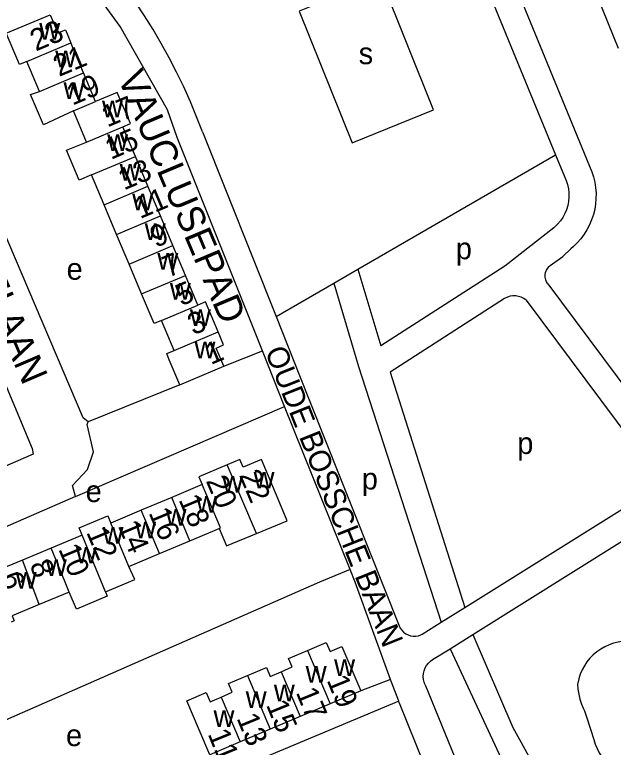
# Model space of a CAD drawing. Extents: x 157768 to 159790, y 387230 to 389604.
# Drawn here: x 158864.1 to 158974.5, y 388469.5 to 388604.7 of the extents above; entities that cross this region are included whole.
import ezdxf

# ---------------------------------------------------------------- set-up
doc = ezdxf.new("R2010")
doc.units = 0
for name, color, linetype in [('BLT_Basislijn', 7, 'Continuous'), ('BLT_Bebouwing', 7, 'Continuous'), ('BLT_Centroide', 7, 'Continuous'), ('BLT_Huisnummer', 7, 'Continuous'), ('BLT_Huisnummer_ tussenligend', 7, 'Continuous'), ('BLT_Onderverdeling_panden', 7, 'Continuous'), ('BLT_Straatnaam', 7, 'Continuous'), ('BLT_Straatnaam_verkleind', 7, 'Continuous')]:
    doc.layers.add(name, color=color, linetype=linetype)

msp = doc.modelspace()

# ---------------------------------------------------------------- linework, layer by layer
at = {"layer": 'BLT_Basislijn'}
for p, q in [((158975.41, 388598.44), (158950.82, 388659.43)), ((158945.06, 388637.67), (158970.49, 388575.7)), ((158940.42, 388635.8), (158963.8, 388578.82)), ((158898.7, 388583.02), (158912.26, 388549)), ((158927.34, 388557.72), (158963.8, 388578.82)), ((158963.8, 388578.82), (158965.76, 388574.06)), ((158963.46, 388565.36), (158954.48, 388558.29)), ((158954.48, 388558.29), (158931.57, 388543.58)), ((158922.89, 388555.15), (158927.34, 388557.72)), ((158927.34, 388557.72), (158931.57, 388543.58)), ((158912.26, 388549), (158922.89, 388555.15)), ((158922.89, 388555.15), (158927.49, 388539.78)), ((158962.37, 388554.99), (158987.75, 388521)), ((158954.4, 388552.33), (158933.31, 388538.75)), ((158958.37, 388552), (158983.58, 388518.22)), ((158912.26, 388549), (158916.6, 388538.1)), ((158902.62, 388539.82), (158909.76, 388542.67)), ((158913.81, 388532.41), (158909.76, 388542.67)), ((158927.49, 388539.78), (158942.71, 388492.62)), ((158916.6, 388538.1), (158918.5, 388533.34)), ((158933.31, 388538.75), (158947.09, 388495.36)), ((158894.53, 388536.41), (158877.6, 388529.55)), ((158918.5, 388533.34), (158934.98, 388491.97)), ((158875.29, 388515.8), (158913.81, 388532.41)), ((158925.92, 388502.32), (158913.81, 388532.41)), ((158875.29, 388515.8), (158843.47, 388502.02)), ((158942.71, 388492.62), (158947.09, 388495.36)), ((158939.2, 388490.42), (158942.71, 388492.62)), ((158944.35, 388487.74), (158948.53, 388490.36)), ((158941.12, 388485.73), (158944.35, 388487.74)), ((158933.36, 388482.07), (158927.87, 388479.94)), ((158939.77, 388481.05), (158952.53, 388449.95)), ((158934.99, 388477.78), (158934.88, 388478.07)), ((158934.99, 388477.78), (158941.62, 388461.3)), ((158969.15, 388476.3), (158969.56, 388475.02)), ((158969.56, 388475.02), (158970.86, 388470.97))]:
    msp.add_line(p, q, dxfattribs=at)
for points in [[(158898.7, 388583.02), (158897.62, 388585.82), (158896.46, 388588.59), (158895.23, 388591.32), (158893.93, 388594.02), (158892.55, 388596.69), (158891.11, 388599.32), (158889.59, 388601.9), (158888.01, 388604.45), (158886.36, 388606.96), (158884.64, 388609.41), (158882.86, 388611.83), (158881.01, 388614.19), (158879.11, 388616.5), (158877.14, 388618.77), (158875.11, 388620.98), (158873.02, 388623.13), (158870.88, 388625.23), (158870.12, 388625.94)], [(158909.76, 388542.67), (158894.06, 388582.03), (158892.27, 388587.1), (158883.51, 388602.46), (158877.81, 388610.42), (158874.98, 388613.54)], [(158916.51, 388605.32), (158926.27, 388581.03), (158941.32, 388587.12), (158931.57, 388611.37), (158916.51, 388605.32)], [(158877.6, 388529.55), (158876.7, 388530.29), (158849.23, 388594.74), (158848.78, 388595.18)], [(158970.49, 388575.7), (158970.8, 388574.74), (158971.03, 388573.76), (158971.19, 388572.76), (158971.27, 388571.76), (158971.26, 388570.75), (158971.18, 388569.75), (158971.02, 388568.75), (158970.78, 388567.78), (158970.46, 388566.82), (158970.07, 388565.89), (158969.6, 388565), (158969.07, 388564.15), (158968.47, 388563.34), (158967.81, 388562.58), (158967.09, 388561.88), (158966.63, 388561.49)], [(158965.76, 388574.06), (158966, 388573.32), (158966.17, 388572.55), (158966.26, 388571.77), (158966.27, 388570.99), (158966.2, 388570.21), (158966.05, 388569.44), (158965.82, 388568.69), (158965.52, 388567.97), (158965.14, 388567.28), (158964.7, 388566.64), (158964.19, 388566.04), (158963.63, 388565.49), (158963.46, 388565.36)], [(158962.83, 388558.39), (158965.14, 388560.05), (158966.63, 388561.49)], [(158962.37, 388554.99), (158962.14, 388555.37), (158961.99, 388555.78), (158961.9, 388556.22), (158961.9, 388556.66), (158961.98, 388557.1), (158962.13, 388557.51), (158962.36, 388557.89), (158962.65, 388558.23), (158962.83, 388558.39)], [(158958.37, 388552), (158957.94, 388552.3), (158957.48, 388552.54), (158956.98, 388552.71), (158956.46, 388552.79), (158955.94, 388552.8), (158955.42, 388552.73), (158954.92, 388552.58), (158954.4, 388552.33)], [(158856.2, 388551.05), (158867.29, 388524.65), (158867.48, 388523.59), (158843.07, 388513.05)], [(158875.29, 388515.8), (158874.72, 388517.84), (158877.52, 388520.77), (158878.59, 388524.05), (158877.42, 388529.06), (158877.6, 388529.55)], [(158948.53, 388490.36), (158985.19, 388513.29), (158991.08, 388517.21), (159005.1, 388524.86)], [(158947.09, 388495.36), (158982.47, 388517.49), (158983.58, 388518.22)], [(158925.92, 388502.32), (158920.27, 388500), (158858.27, 388472.75)], [(158933.36, 388482.07), (158926.83, 388500), (158925.92, 388502.32)], [(158934.98, 388491.97), (158935.18, 388491.53), (158935.46, 388491.13), (158935.79, 388490.78), (158936.18, 388490.49), (158936.61, 388490.27), (158937.07, 388490.12), (158937.55, 388490.05), (158938.04, 388490.05), (158938.51, 388490.14), (158938.97, 388490.31), (158939.2, 388490.42)], [(158948.53, 388490.36), (158955.94, 388473.21), (158957.78, 388469.86)], [(158977.06, 388489.15), (158976.2, 388489.1), (158975.34, 388488.97), (158974.49, 388488.76), (158973.68, 388488.47), (158972.89, 388488.11), (158972.13, 388487.68), (158971.42, 388487.18), (158970.76, 388486.62), (158970.15, 388486), (158969.6, 388485.32), (158969.12, 388484.6), (158968.7, 388483.84), (158968.36, 388483.04), (158968.09, 388482.21), (158967.9, 388481.37), (158967.88, 388481.24)], [(158944.35, 388487.74), (158955.86, 388463.01), (158960.62, 388453.61), (158960.67, 388453.29), (158960.25, 388452.97), (158952.53, 388449.95)], [(158939.77, 388481.05), (158939.58, 388481.55), (158939.45, 388482.08), (158939.41, 388482.61), (158939.45, 388483.15), (158939.56, 388483.68), (158939.76, 388484.19), (158940.02, 388484.66), (158940.35, 388485.08), (158940.74, 388485.46), (158941.12, 388485.73)], [(158934.88, 388478.07), (158933.55, 388481.54), (158933.36, 388482.07)], [(158967.88, 388481.24), (158967.94, 388480.29), (158968.08, 388479.36), (158968.3, 388478.43), (158968.6, 388477.53), (158968.97, 388476.66), (158969.15, 388476.3)], [(158934.88, 388478.07), (158911.01, 388468.07), (158915.99, 388456.66)], [(158970.86, 388470.97), (158971.12, 388470.14), (158971.46, 388469.34), (158971.86, 388468.56), (158972.34, 388467.83), (158972.88, 388467.15), (158973.49, 388466.52), (158974.14, 388465.94), (158974.85, 388465.43), (158975.6, 388464.99), (158976.39, 388464.61), (158977.21, 388464.31), (158978.06, 388464.09), (158978.92, 388463.94), (158979.79, 388463.88), (158980.66, 388463.89), (158981.53, 388463.98), (158982.38, 388464.16), (158983.22, 388464.41), (158983.99, 388464.71)], [(158957.78, 388469.86), (158966.52, 388453.88), (158973.85, 388442.88), (158989.79, 388420.06), (158996.14, 388409.83)]]:
    msp.add_lwpolyline(points, dxfattribs=at)
at = {"layer": 'BLT_Bebouwing'}
for p, q in [((158876.76, 388593.92), (158874.43, 388599.44)), ((158868.65, 388590.5), (158866.33, 388596.02)), ((158878.99, 388588.62), (158876.76, 388593.92)), ((158877.33, 388581.17), (158874.91, 388586.9)), ((158886.32, 388578.5), (158884.01, 388583.98)), ((158888.63, 388573.02), (158886.32, 388578.5)), ((158880.55, 388569.61), (158878.24, 388575.1)), ((158890.94, 388567.54), (158888.63, 388573.02)), ((158882.86, 388564.13), (158880.55, 388569.61)), ((158893.25, 388562.06), (158890.94, 388567.54)), ((158885.17, 388558.65), (158882.86, 388564.13)), ((158895.56, 388556.58), (158893.25, 388562.06)), ((158887.48, 388553.17), (158885.17, 388558.65)), ((158897.87, 388551.1), (158895.56, 388556.58)), ((158893.49, 388542.73), (158891.15, 388548.27)), ((158894.53, 388536.41), (158902.62, 388539.82)), ((158898.64, 388517.99), (158893.02, 388515.63)), ((158893.02, 388515.63), (158887.4, 388513.27)), ((158887.4, 388513.27), (158881.78, 388510.91)), ((158876.49, 388508.7), (158870.78, 388506.3)), ((158890.76, 388505.27), (158896.38, 388507.64)), ((158870.78, 388506.3), (158865.49, 388504.07)), ((158865.49, 388504.07), (158859.91, 388501.73)), ((158874.13, 388498.18), (158868.6, 388495.86)), ((158927.87, 388479.94), (158922.25, 388477.56)), ((158922.25, 388477.56), (158916.72, 388475.22)), ((158916.72, 388475.22), (158911.19, 388472.88)), ((158911.19, 388472.88), (158905.66, 388470.54)), ((158905.66, 388470.54), (158900.04, 388468.16))]:
    msp.add_line(p, q, dxfattribs=at)
for points in [[(158866.33, 388596.02), (158864.95, 388595.44), (158864.45, 388596.63), (158862.51, 388601.23), (158870.62, 388604.65), (158872.04, 388601.29), (158873.41, 388601.87), (158874.43, 388599.44)], [(158874.91, 388586.9), (158869.38, 388584.31), (158867.01, 388589.94), (158868.65, 388590.5)], [(158884.01, 388583.98), (158885.4, 388584.57), (158882.98, 388590.3), (158878.99, 388588.62)], [(158878.24, 388575.1), (158875.96, 388574.13), (158873.64, 388579.64), (158877.33, 388581.17)], [(158891.15, 388548.27), (158889.79, 388547.69), (158887.48, 388553.17)], [(158901.6, 388546.15), (158899.26, 388551.68), (158897.87, 388551.1)], [(158902.62, 388539.82), (158901.2, 388543.18), (158902.6, 388543.77), (158901.6, 388546.15)], [(158894.53, 388536.41), (158892.58, 388541.02), (158892.11, 388542.15), (158893.49, 388542.73)], [(158908.64, 388508.96), (158914.33, 388511.3), (158912.96, 388514.57), (158909.57, 388522.63), (158906.19, 388521.21), (158905.6, 388522.61), (158903.28, 388521.63)], [(158903.28, 388521.63), (158898.03, 388519.42), (158898.64, 388517.99)], [(158876.49, 388508.7), (158875.94, 388510), (158881.22, 388512.22), (158881.78, 388510.91)], [(158896.38, 388507.64), (158901.78, 388509.91)], [(158901.78, 388509.91), (158903.13, 388506.69), (158908.64, 388508.96)], [(158885.14, 388502.91), (158890.76, 388505.27)], [(158880.82, 388498.2), (158886.22, 388500.5), (158885.14, 388502.91)], [(158880.82, 388498.2), (158881.14, 388497.44), (158875.44, 388495.04), (158874.13, 388498.18)], [(158868.6, 388495.86), (158863.62, 388493.77), (158863.99, 388492.89), (158863.39, 388492.64)], [(158918.08, 388487.41), (158921.53, 388488.87), (158922.23, 388487.2), (158924.4, 388488.12), (158927.87, 388479.94)], [(158913.21, 388483.5), (158915.25, 388484.37), (158914.58, 388485.93), (158916.92, 388486.92), (158918.08, 388487.41)], [(158906.99, 388482.8), (158910.49, 388484.28), (158911.18, 388482.64), (158913.21, 388483.5)], [(158902.14, 388478.83), (158904.18, 388479.7), (158903.5, 388481.32), (158906.99, 388482.8)], [(158900.04, 388468.16), (158898.09, 388472.76), (158895.82, 388478.12), (158899.39, 388479.64), (158900.1, 388477.97), (158902.14, 388478.83)]]:
    msp.add_lwpolyline(points, dxfattribs=at)
at = {"layer": 'BLT_Onderverdeling_panden'}
for p, q in [((158866.33, 388596.02), (158874.43, 388599.44)), ((158868.65, 388590.5), (158876.76, 388593.92)), ((158874.91, 388586.9), (158878.99, 388588.62)), ((158877.33, 388581.17), (158884.01, 388583.98)), ((158878.24, 388575.1), (158886.32, 388578.5)), ((158880.55, 388569.61), (158888.63, 388573.02)), ((158882.86, 388564.13), (158890.94, 388567.54)), ((158885.17, 388558.65), (158893.25, 388562.06)), ((158887.48, 388553.17), (158895.56, 388556.58)), ((158891.15, 388548.27), (158897.87, 388551.1)), ((158893.49, 388542.73), (158901.6, 388546.15)), ((158908.64, 388508.96), (158903.28, 388521.63)), ((158902, 388510), (158898.64, 388517.99)), ((158896.38, 388507.64), (158893.02, 388515.63)), ((158890.76, 388505.27), (158887.4, 388513.27)), ((158885.14, 388502.91), (158881.78, 388510.91)), ((158880.82, 388498.2), (158876.49, 388508.7)), ((158918.08, 388487.41), (158922.25, 388477.56)), ((158906.99, 388482.8), (158911.19, 388472.88)), ((158913.21, 388483.5), (158916.72, 388475.22)), ((158902.14, 388478.83), (158905.66, 388470.54))]:
    msp.add_line(p, q, dxfattribs=at)
for points in [[(158901.78, 388509.91), (158902, 388510)], [(158874.13, 388498.18), (158873.37, 388500), (158870.78, 388506.3)], [(158868.6, 388495.86), (158867.03, 388500), (158865.49, 388504.07)]]:
    msp.add_lwpolyline(points, dxfattribs=at)

# ---------------------------------------------------------------- texts
at = {"layer": 'BLT_Centroide'}
for s, p in [('w', (158868.59, 388600.03)), ('w', (158871.54, 388594.97)), ('s', (158927.5, 388595.52)), ('w', (158873.07, 388589.12)), ('w', (158880.16, 388585.75)), ('w', (158881.12, 388579.53)), ('w', (158883.43, 388574.06)), ('w', (158885.74, 388568.56)), ('w', (158888.05, 388563.09)), ('p', (158945.41, 388559.55)), ('w', (158890.37, 388557.62)), ('e', (158873.64, 388555.77)), ('w', (158892.68, 388552.12)), ('w', (158896.38, 388547.22)), ('w', (158897.23, 388541.28)), ('p', (158956.74, 388523.64)), ('w', (158902.34, 388516.52)), ('w', (158908.12, 388517.28)), ('p', (158928.07, 388517.09)), ('e', (158877.15, 388514.78)), ('w', (158897.52, 388512.83)), ('w', (158891.89, 388510.45)), ('w', (158886.27, 388508.08)), ('w', (158880.27, 388507.09)), ('w', (158875.34, 388503.45)), ('w', (158869.81, 388501.12)), ('w', (158864.25, 388498.8)), ('w', (158922.97, 388482.69)), ('w', (158917.73, 388481.45)), ('w', (158911.86, 388478.05)), ('w', (158906.67, 388476.81)), ('w', (158900.73, 388473.33)), ('e', (158873.53, 388469.78))]:
    msp.add_text(s, height=4, dxfattribs=at).set_placement(p)
at = {"layer": 'BLT_Huisnummer'}
for s, rotation, p in [('23', 22.8593, (158867.96, 388597.84)), ('17', 22.8593, (158881.14, 388583.82)), ('13', 22.8593, (158884.21, 388572.22)), ('9', 22.8593, (158890.08, 388561.62)), ('5', 22.8593, (158894.77, 388550.86)), ('1', 22.8593, (158900.23, 388540.03)), ('22', 292.8103, (158905.4, 388519.77)), ('18', 292.8103, (158894.25, 388515.24)), ('14', 292.8103, (158883.04, 388510.44)), ('10', 292.8103, (158872.07, 388506.13)), ('6', 292.8103, (158861.34, 388500.99)), ('19', 292.2771, (158921.56, 388481.96)), ('15', 292.2771, (158910.38, 388477.39)), ('11', 292.2771, (158899.62, 388472.04))]:
    msp.add_text(s, height=4, rotation=rotation, dxfattribs=at).set_placement(p)
at = {"layer": 'BLT_Huisnummer_ tussenligend'}
for s, rotation, p in [('21', 22.8593, (158872.24, 388593.15)), ('19', 22.8593, (158874.7, 388587.85)), ('15', 22.8593, (158881.8, 388577.86)), ('11', 22.8593, (158887.18, 388566.94)), ('7', 22.8593, (158892.34, 388556.09)), ('3', 22.8593, (158897, 388545.49)), ('20', 292.8103, (158899.28, 388518.71)), ('16', 292.8103, (158888.71, 388512.83)), ('12', 292.8103, (158877.22, 388509.22)), ('8', 292.8103, (158866.75, 388503.2)), ('17', 292.2771, (158915.87, 388479.7)), ('13', 292.2771, (158904.94, 388474.94))]:
    msp.add_text(s, height=4, rotation=rotation, dxfattribs=at).set_placement(p)
at = {"layer": 'BLT_Straatnaam'}
for s, height, rotation, p in [('VAUCLUSEPAD', 5, 292.842, (158882.97, 388593.12)), ('DAUPHINELAAN', 4.9999, 293.1356, (158845.27, 388583.92))]:
    msp.add_text(s, height=height, rotation=rotation, dxfattribs=at).set_placement(p)
at = {"layer": 'BLT_Straatnaam_verkleind'}
msp.add_text('OUDE BOSSCHE BAAN', height=4, rotation=291.7882, dxfattribs=at).set_placement((158910.16, 388542.59))

doc.saveas('drawing.dxf')
